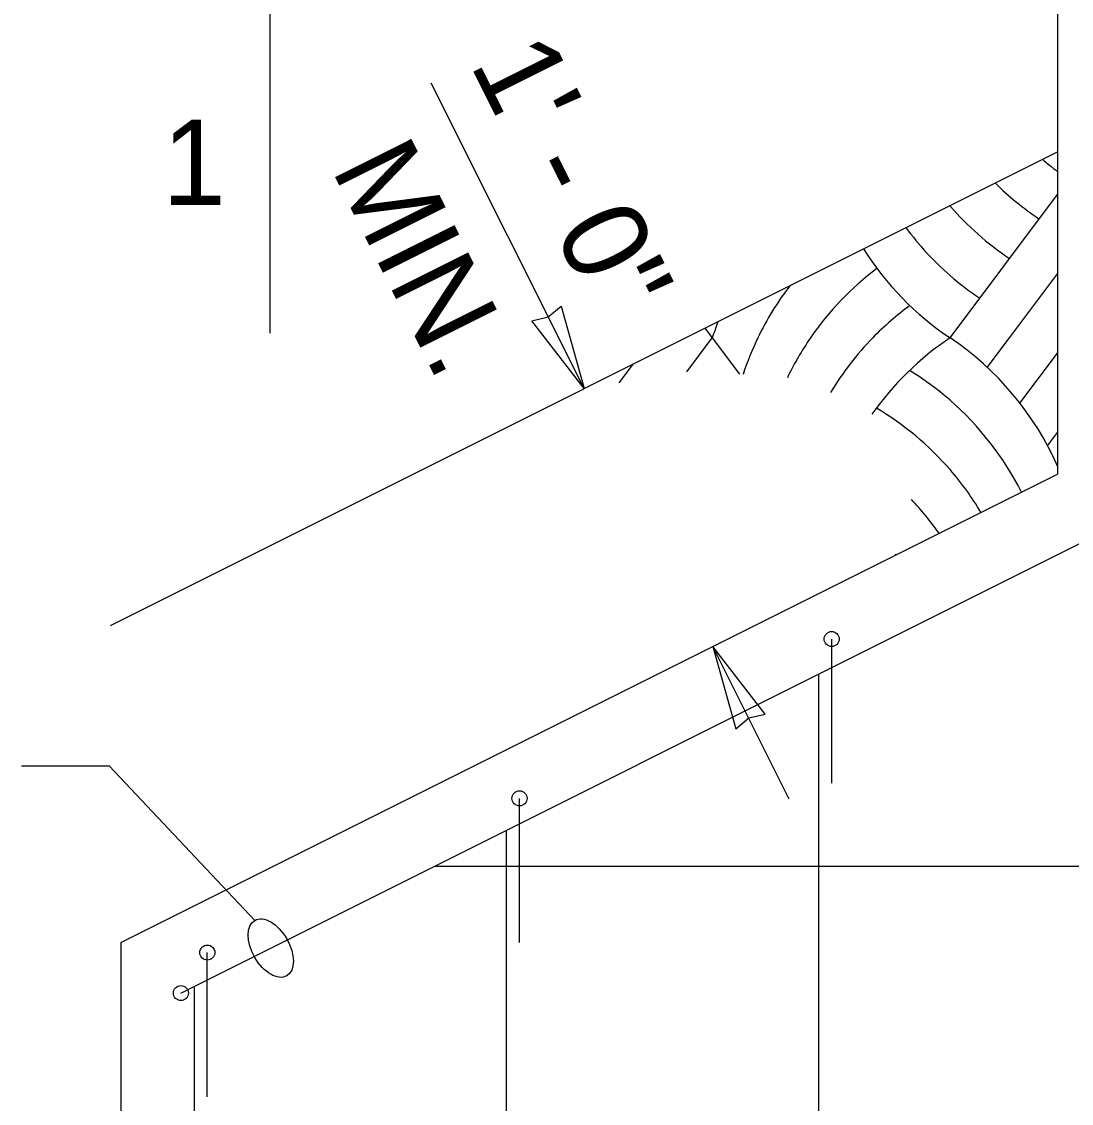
# Model space of a CAD drawing. Extents: x 99862 to 104211, y 98939 to 105076.
# Drawn here: x 101887.6 to 102084.3, y 101668.3 to 101871 of the extents above; entities that cross this region are included whole.
import ezdxf

# ---------------------------------------------------------------- set-up
doc = ezdxf.new("R2010")
doc.units = 0
for name, color, linetype in [('Level 10', 7, 'Continuous'), ('Level 15', 7, 'Continuous'), ('Level 2', 7, 'Continuous'), ('Level 20', 7, 'Continuous'), ('Level 7', 7, 'Continuous'), ('Level 9', 7, 'Continuous')]:
    doc.layers.add(name, color=color, linetype=linetype)

msp = doc.modelspace()

# ---------------------------------------------------------------- linework, layer by layer
at = {"layer": 'Level 10'}
for p, q in [((101917.45, 101689.01), (102208.48, 101834.53)), ((102039.39, 101728.33), (102039.39, 101755.33)), ((102036.92, 101748.75), (102036.92, 101659.02)), ((101980.9, 101698.48), (101980.9, 101725.48)), ((101978.42, 101719.5), (101978.42, 101659.02)), ((102434.95, 101712.74), (101964.89, 101712.74)), ((101922.4, 101669.59), (101922.4, 101696.59)), ((101919.92, 101690.25), (101919.92, 101659.02))]:
    msp.add_line(p, q, dxfattribs=at)
for centre in [(102039.39, 101755.33), (101980.9, 101725.48), (101922.4, 101696.59), (101917.45, 101689.01)]:
    msp.add_circle(centre, 1.41, dxfattribs=at)
at = {"layer": 'Level 15'}
for p, q in [((101992.99, 101802.25), (101964.36, 101859.49)), ((102031.45, 101725.33), (102017.14, 101753.95)), ((101887.61, 101731.56), (101904.01, 101731.56)), ((101904.01, 101731.56), (101931.28, 101702.62))]:
    msp.add_line(p, q, dxfattribs=at)
msp.add_ellipse((101934.28, 101697.43), major_axis=(-3, 5.2), ratio=0.57735, dxfattribs=at)
at = {"layer": 'Level 2'}
for p, q in [((102081.7, 101995.1), (102081.7, 101786.23)), ((101906.2, 101698.48), (102081.7, 101786.23)), ((101906.2, 101698.48), (101906.2, 101659.02))]:
    msp.add_line(p, q, dxfattribs=at)
at = {"layer": 'Level 20'}
msp.add_line((101934.12, 101876.64), (101934.12, 101812.64), dxfattribs=at)
at = {"layer": 'Level 7'}
for points in [[(101992.99, 101802.25), (101983.2, 101814.94), (101986.28, 101815.66), (101988.71, 101817.69)], [(102017.14, 101753.95), (102021.41, 101738.51), (102023.84, 101740.54), (102026.93, 101741.26)]]:
    msp.add_lwpolyline(points, close=True, dxfattribs=at)
at = {"layer": 'Level 9'}
for p, q in [((101904.27, 101757.89), (102081.7, 101846.61)), ((102061.57, 101811.75), (102081.7, 101838.59)), ((102072.71, 101811.75), (102081.7, 101823.74)), ((102012.25, 101805.39), (102017.02, 101811.75)), ((102015.65, 101813.58), (102017.02, 101811.75)), ((102017.02, 101811.75), (102022.14, 101804.93)), ((102068.55, 101806.21), (102072.71, 101811.75)), ((102074.67, 101799.51), (102081.7, 101808.89)), ((101999.56, 101803.32), (102002.23, 101806.87)), ((102079.83, 101791.55), (102081.7, 101794.04))]:
    msp.add_line(p, q, dxfattribs=at)
for centre, start, end in [((102115.28, 101888.23), 229.7703, 233.4272), ((102109.71, 101880.8), 225.2517, 236.0964), ((102104.15, 101873.38), 220.8501, 220.9416), ((102104.15, 101873.38), 220.9415, 236.0964), ((102098.58, 101865.96), 216.5338, 228.9599), ((102093.01, 101858.53), 212.2741, 236.0964), ((102081.87, 101779.81), 127.1006, 145.4911), ((102098.58, 101865.96), 228.9599, 236.0964), ((102076.31, 101787.24), 142.5061, 154.2266), ((102087.44, 101772.39), 126.331, 135.7128), ((102070.74, 101794.66), 159.0675, 162.3566), ((102076.31, 101787.24), 154.2265, 161.7415), ((102081.87, 101779.81), 145.491, 154.2882), ((102087.44, 101772.39), 135.7127, 148.8874), ((102093.01, 101764.97), 123.9036, 144.845), ((102030.13, 101764.97), 23.8064, 56.0963), ((102024.56, 101757.54), 48.9597, 58.5465), ((102024.56, 101757.54), 26.6753, 48.9597), ((102018.99, 101750.12), 40.9413, 59.3021), ((102018.99, 101750.12), 30.8984, 40.9414), ((102013.42, 101742.69), 35.1459, 43.4704), ((102007.86, 101735.27), 39.4409, 39.6618)]:
    msp.add_arc(centre, 56.37, start, end, dxfattribs=at)

# ---------------------------------------------------------------- texts
at = {"layer": 'Level 20'}
for s, p in [('1\' - 0"', (101971.52, 101863.07)), (' MIN.', (101942.9, 101848.76))]:
    msp.add_text(s, height=16, rotation=296.565, dxfattribs=at).set_placement(p)
msp.add_text('1', height=16, dxfattribs=at).set_placement((101913.96, 101836.64))

doc.saveas('drawing.dxf')
